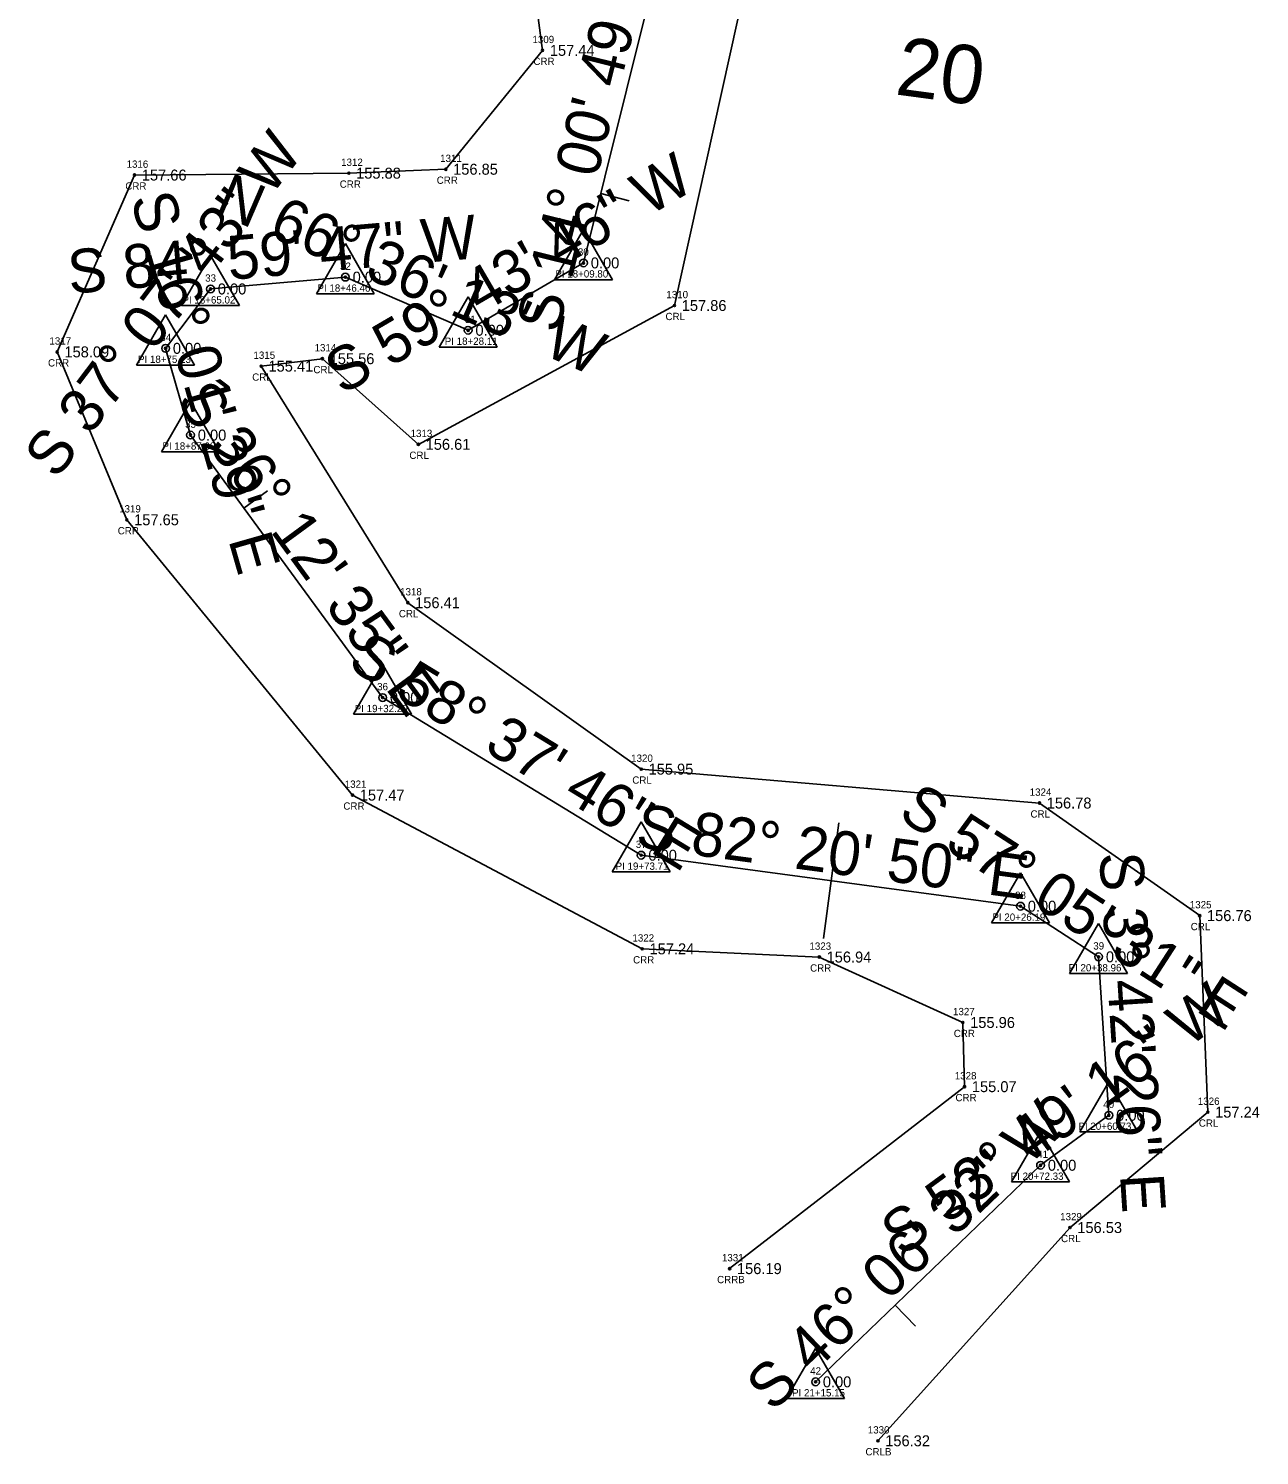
# Model space of a CAD drawing. Extents: x 2279339 to 2281902, y 1061267 to 1062892.
# Drawn here: x 2280217.3 to 2280386.1, y 1061385.9 to 1061581.5 of the extents above; entities that cross this region are included whole.
import ezdxf

# ---------------------------------------------------------------- set-up
doc = ezdxf.new("R2010")
doc.units = 0
for name, color, linetype in [('RD_EX_H2O', 7, 'Continuous'), ('RD_EX_H2O_txCode', 7, 'Continuous'), ('RD_EX_TX_H2O_ELEV', 7, 'Continuous'), ('RD_HC_Cl', 7, 'Continuous'), ('RD_HC_Data', 7, 'Continuous'), ('RD_HC_Data_Tic', 7, 'Continuous'), ('RD_HC_Survey_ELEV', 7, 'Continuous'), ('RD_HC_TX_Sta50', 7, 'Continuous'), ('RD_HC_txCode', 7, 'Continuous'), ('RD_SMD_Locator', 7, 'Continuous')]:
    doc.layers.add(name, color=color, linetype=linetype)

msp = doc.modelspace()

# ---------------------------------------------------------------- linework, layer by layer
at = {"layer": 'RD_EX_H2O'}
for points in [[(2280269.9, 1061794.49), (2280270.02, 1061790.74), (2280293.77, 1061763.48), (2280320.49, 1061735.05), (2280335.4, 1061680.01), (2280309.48, 1061674.63), (2280300.03, 1061660.41), (2280304.47, 1061633.12), (2280315.65, 1061587.64), (2280305.89, 1061543.57), (2280270.77, 1061524.54), (2280257.61, 1061536.28), (2280249.22, 1061535.26), (2280269.33, 1061502.83), (2280301.34, 1061480.02), (2280355.94, 1061475.37), (2280377.91, 1061459.94), (2280379.03, 1061433), (2280360.13, 1061417.18), (2280333.79, 1061387.95)], [(2280219.49, 1061771.9), (2280219.45, 1061768.68), (2280220.02, 1061767.07), (2280223.01, 1061764.94), (2280232.42, 1061752.34), (2280266.07, 1061747.74), (2280284.73, 1061725.48), (2280294.86, 1061698.39), (2280278.35, 1061688.54), (2280267.33, 1061659.35), (2280270.69, 1061629.09), (2280284.25, 1061605.42), (2280287.8, 1061578.54), (2280274.54, 1061562.25), (2280261.24, 1061561.71), (2280231.85, 1061561.45), (2280221.24, 1061537.21), (2280230.8, 1061514.2), (2280261.74, 1061476.46), (2280301.47, 1061455.38), (2280325.75, 1061454.26), (2280345.44, 1061445.29), (2280345.67, 1061436.49), (2280313.46, 1061411.55)]]:
    msp.add_lwpolyline(points, dxfattribs=at)
at = {"layer": 'RD_HC_Cl'}
for p, q in [((2280302.26, 1061584.82), (2280293.42, 1061549.41)), ((2280293.42, 1061549.41), (2280277.6, 1061540.18)), ((2280242.27, 1061545.84), (2280236.11, 1061537.7)), ((2280260.76, 1061547.46), (2280242.27, 1061545.84)), ((2280277.6, 1061540.18), (2280260.76, 1061547.46)), ((2280236.11, 1061537.7), (2280239.53, 1061525.81)), ((2280239.53, 1061525.81), (2280265.87, 1061489.83)), ((2280265.87, 1061489.83), (2280301.32, 1061468.22)), ((2280301.32, 1061468.22), (2280353.34, 1061461.23)), ((2280353.34, 1061461.23), (2280364.05, 1061454.29)), ((2280364.05, 1061454.29), (2280365.46, 1061432.57)), ((2280365.46, 1061432.57), (2280356.09, 1061425.72)), ((2280356.09, 1061425.72), (2280325.24, 1061396.03))]:
    msp.add_line(p, q, dxfattribs=at)
at = {"layer": 'RD_HC_Data'}
for p, q in [((2280289.45, 1061547.11), (2280293.42, 1061553.99)), ((2280293.42, 1061553.99), (2280297.39, 1061547.11)), ((2280256.79, 1061545.17), (2280260.77, 1061552.05)), ((2280260.77, 1061552.05), (2280264.73, 1061545.17)), ((2280238.3, 1061543.55), (2280242.27, 1061550.43)), ((2280242.27, 1061550.43), (2280246.24, 1061543.55)), ((2280289.45, 1061547.11), (2280297.39, 1061547.11)), ((2280238.3, 1061543.55), (2280246.24, 1061543.55)), ((2280256.79, 1061545.17), (2280264.73, 1061545.17)), ((2280273.63, 1061537.88), (2280277.61, 1061544.76)), ((2280277.61, 1061544.76), (2280281.57, 1061537.88)), ((2280232.14, 1061535.41), (2280236.11, 1061542.29)), ((2280236.11, 1061542.29), (2280240.08, 1061535.41)), ((2280273.63, 1061537.88), (2280281.57, 1061537.88)), ((2280232.14, 1061535.41), (2280240.08, 1061535.41)), ((2280235.56, 1061523.52), (2280239.53, 1061530.4)), ((2280239.53, 1061530.4), (2280243.5, 1061523.52)), ((2280235.56, 1061523.52), (2280243.5, 1061523.52)), ((2280261.9, 1061487.54), (2280265.87, 1061494.42)), ((2280265.87, 1061494.42), (2280269.84, 1061487.54)), ((2280261.9, 1061487.54), (2280269.84, 1061487.54)), ((2280297.35, 1061465.92), (2280301.32, 1061472.8)), ((2280301.32, 1061472.8), (2280305.29, 1061465.92)), ((2280297.35, 1061465.92), (2280305.29, 1061465.92)), ((2280349.36, 1061458.94), (2280353.34, 1061465.82)), ((2280353.34, 1061465.82), (2280357.31, 1061458.94)), ((2280349.36, 1061458.94), (2280357.31, 1061458.94)), ((2280360.08, 1061452), (2280364.05, 1061458.88)), ((2280364.05, 1061458.88), (2280368.02, 1061452)), ((2280360.08, 1061452), (2280368.02, 1061452)), ((2280361.49, 1061430.28), (2280365.46, 1061437.16)), ((2280365.46, 1061437.16), (2280369.43, 1061430.28)), ((2280352.12, 1061423.43), (2280356.09, 1061430.31)), ((2280356.09, 1061430.31), (2280360.06, 1061423.43)), ((2280361.49, 1061430.28), (2280369.43, 1061430.28)), ((2280352.12, 1061423.43), (2280360.06, 1061423.43)), ((2280321.27, 1061393.74), (2280325.24, 1061400.62)), ((2280325.24, 1061400.62), (2280329.21, 1061393.74)), ((2280321.27, 1061393.74), (2280329.21, 1061393.74))]:
    msp.add_line(p, q, dxfattribs=at)
for centre in [(2280293.42, 1061549.41), (2280260.76, 1061547.46), (2280242.27, 1061545.84), (2280277.6, 1061540.18), (2280236.11, 1061537.7), (2280239.53, 1061525.81), (2280265.87, 1061489.83), (2280301.32, 1061468.22), (2280353.34, 1061461.23), (2280364.05, 1061454.29), (2280365.46, 1061432.57), (2280356.09, 1061425.72), (2280325.24, 1061396.03)]:
    msp.add_circle(centre, 0.529, dxfattribs=at)
at = {"layer": 'RD_HC_Data_Tic'}
for p, q in [((2280295.79, 1061558.91), (2280299.67, 1061557.94)), ((2280246.85, 1061515.81), (2280250.08, 1061518.17)), ((2280327.37, 1061464.72), (2280328.44, 1061472.65)), ((2280327.37, 1061464.72), (2280326.31, 1061456.79)), ((2280336.15, 1061406.54), (2280338.93, 1061403.65))]:
    msp.add_line(p, q, dxfattribs=at)
at = {"layer": 'RD_SMD_Locator'}
for centre in [(2280287.8, 1061578.54), (2280231.85, 1061561.45), (2280261.24, 1061561.71), (2280274.54, 1061562.25), (2280293.42, 1061549.41), (2280260.76, 1061547.46), (2280242.27, 1061545.84), (2280305.89, 1061543.57), (2280277.6, 1061540.18), (2280236.11, 1061537.7), (2280221.24, 1061537.21), (2280257.61, 1061536.28), (2280249.22, 1061535.26), (2280239.53, 1061525.81), (2280270.77, 1061524.54), (2280230.8, 1061514.2), (2280269.33, 1061502.83), (2280265.87, 1061489.83), (2280301.34, 1061480.02), (2280261.74, 1061476.46), (2280355.94, 1061475.37), (2280301.32, 1061468.22), (2280353.34, 1061461.23), (2280377.91, 1061459.94), (2280301.47, 1061455.38), (2280325.75, 1061454.26), (2280364.05, 1061454.29), (2280345.44, 1061445.29), (2280345.67, 1061436.49), (2280365.46, 1061432.57), (2280379.03, 1061433), (2280356.09, 1061425.72), (2280360.13, 1061417.18), (2280313.46, 1061411.55), (2280325.24, 1061396.03), (2280333.79, 1061387.95)]:
    msp.add_circle(centre, 0.15, dxfattribs=at)

# ---------------------------------------------------------------- texts
at = {"layer": 'RD_EX_H2O_txCode'}
for s, p in [('1309', (2280286.42, 1061579.54)), ('CRR', (2280286.55, 1061576.54)), ('1316', (2280230.76, 1061562.45)), ('1312', (2280260.18, 1061562.71)), ('1311', (2280273.76, 1061563.25)), ('CRR', (2280273.29, 1061560.25)), ('CRR', (2280230.59, 1061559.45)), ('CRR', (2280259.99, 1061559.71)), ('1310', (2280304.78, 1061544.57)), ('CRL', (2280304.66, 1061541.57)), ('1317', (2280220.18, 1061538.21)), ('1314', (2280256.54, 1061537.28)), ('CRR', (2280219.99, 1061535.21)), ('1315', (2280248.16, 1061536.26)), ('CRL', (2280247.99, 1061533.26)), ('CRL', (2280256.38, 1061534.28)), ('1313', (2280269.71, 1061525.54)), ('CRL', (2280269.54, 1061522.54)), ('1319', (2280229.74, 1061515.2)), ('CRR', (2280229.55, 1061512.2)), ('1318', (2280268.27, 1061503.83)), ('CRL', (2280268.1, 1061500.83)), ('1320', (2280299.95, 1061481.02)), ('CRL', (2280300.11, 1061478.02)), ('1321', (2280260.68, 1061477.46)), ('1324', (2280354.6, 1061476.37)), ('CRR', (2280260.49, 1061474.46)), ('CRL', (2280354.71, 1061473.37)), ('1325', (2280376.56, 1061460.94)), ('CRL', (2280376.68, 1061457.94)), ('1322', (2280300.13, 1061456.38)), ('1323', (2280324.4, 1061455.26)), ('CRR', (2280300.22, 1061453.38)), ('CRR', (2280324.49, 1061452.26)), ('1327', (2280344.09, 1061446.29)), ('CRR', (2280344.19, 1061443.29)), ('1328', (2280344.33, 1061437.49)), ('CRR', (2280344.42, 1061434.49)), ('1326', (2280377.66, 1061434)), ('CRL', (2280377.8, 1061431)), ('1329', (2280358.78, 1061418.18)), ('CRL', (2280358.9, 1061415.18)), ('1331', (2280312.4, 1061412.55)), ('CRRB', (2280311.74, 1061409.55)), ('1330', (2280332.4, 1061388.95)), ('CRLB', (2280332.08, 1061385.95))]:
    msp.add_text(s, height=1, dxfattribs=at).set_placement(p)
at = {"layer": 'RD_EX_TX_H2O_ELEV'}
for s, p in [('157.44', (2280288.8, 1061577.79)), ('157.66', (2280232.85, 1061560.7)), ('155.88', (2280262.24, 1061560.96)), ('156.85', (2280275.54, 1061561.5)), ('157.86', (2280306.89, 1061542.82)), ('158.09', (2280222.24, 1061536.46)), ('155.41', (2280250.22, 1061534.51)), ('155.56', (2280258.61, 1061535.53)), ('156.61', (2280271.77, 1061523.79)), ('157.65', (2280231.8, 1061513.45)), ('156.41', (2280270.33, 1061502.08)), ('155.95', (2280302.34, 1061479.27)), ('157.47', (2280262.74, 1061475.71)), ('156.78', (2280356.94, 1061474.62)), ('156.76', (2280378.91, 1061459.19)), ('157.24', (2280302.47, 1061454.63)), ('156.94', (2280326.75, 1061453.51)), ('155.96', (2280346.44, 1061444.54)), ('155.07', (2280346.67, 1061435.74)), ('157.24', (2280380.03, 1061432.25)), ('156.53', (2280361.13, 1061416.43)), ('156.19', (2280314.46, 1061410.8)), ('156.32', (2280334.79, 1061387.2))]:
    msp.add_text(s, height=1.5, dxfattribs=at).set_placement(p)
at = {"layer": 'RD_HC_Data'}
for s, rotation, p in [('S 14%%d 00\' 49" W', 75.9863, (2280289.94, 1061539.62)), ('S 37%%d 07\' 43" W', 52.8715, (2280221.14, 1061519.59)), ('S 59%%d 43\' 46" W', 30.2706, (2280260.32, 1061531.24)), ('N 66%%d 36\' 13" W', 336.6037, (2280242.67, 1061556.38)), ('S 16%%d 01\' 29" E', 286.0248, (2280231.26, 1061558.22)), ('S 84%%d 59\' 47" W', 5.0036, (2280222.95, 1061545.16)), ('S 36%%d 12\' 35" E', 306.2097, (2280237.41, 1061530.39)), ('S 58%%d 37\' 46" E', 328.6294, (2280260.86, 1061494.06)), ('S 57%%d 05\' 31" E', 327.0919, (2280336.37, 1061473.4)), ('S 82%%d 20\' 50" E', 352.3472, (2280300.46, 1061469.34)), ('S 3%%d 42\' 26" E', 273.7074, (2280364.13, 1061468.48)), ('S 53%%d 49\' 16" W', 36.1788, (2280337.11, 1061413.08)), ('S 46%%d 06\' 32" W', 43.8911, (2280319.37, 1061391.78))]:
    msp.add_text(s, height=6, rotation=rotation, dxfattribs=at).set_placement(p)
at = {"layer": 'RD_HC_Survey_ELEV'}
for p in [(2280294.42, 1061548.66), (2280261.76, 1061546.71), (2280243.27, 1061545.09), (2280278.6, 1061539.43), (2280237.11, 1061536.95), (2280240.53, 1061525.06), (2280266.87, 1061489.08), (2280302.32, 1061467.47), (2280354.34, 1061460.48), (2280365.05, 1061453.54), (2280366.46, 1061431.82), (2280357.09, 1061424.97), (2280326.24, 1061395.28)]:
    msp.add_text('0.00', height=1.5, dxfattribs=at).set_placement(p)
at = {"layer": 'RD_HC_TX_Sta50'}
msp.add_text('20', height=8, rotation=352.3472, dxfattribs=at).set_placement((2280336.01, 1061572.53))
at = {"layer": 'RD_HC_txCode'}
for s, p in [('30', (2280292.65, 1061550.41)), ('32', (2280260.03, 1061548.46)), ('33', (2280241.54, 1061546.84)), ('PI 18+09.80', (2280289.56, 1061547.41)), ('PI 18+46.46', (2280256.94, 1061545.46)), ('PI 18+65.02', (2280238.43, 1061543.84)), ('31', (2280277.15, 1061541.18)), ('34', (2280235.38, 1061538.7)), ('PI 18+28.11', (2280274.39, 1061538.18)), ('PI 18+75.23', (2280232.33, 1061535.7)), ('35', (2280238.79, 1061526.81)), ('PI 18+87.60', (2280235.68, 1061523.81)), ('36', (2280265.12, 1061490.83)), ('PI 19+32.20', (2280262.05, 1061487.83)), ('37', (2280300.59, 1061469.22)), ('PI 19+73.71', (2280297.82, 1061466.22)), ('38', (2280352.6, 1061462.23)), ('PI 20+26.19', (2280349.49, 1061459.23)), ('39', (2280363.32, 1061455.29)), ('PI 20+38.96', (2280359.93, 1061452.29)), ('40', (2280364.69, 1061433.57)), ('PI 20+60.73', (2280361.29, 1061430.57)), ('41', (2280355.64, 1061426.72)), ('PI 20+72.33', (2280351.99, 1061423.72)), ('42', (2280324.5, 1061397.03)), ('PI 21+15.15', (2280322.02, 1061394.03))]:
    msp.add_text(s, height=1, dxfattribs=at).set_placement(p)

doc.saveas('drawing.dxf')
